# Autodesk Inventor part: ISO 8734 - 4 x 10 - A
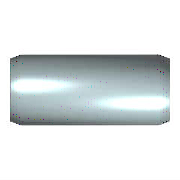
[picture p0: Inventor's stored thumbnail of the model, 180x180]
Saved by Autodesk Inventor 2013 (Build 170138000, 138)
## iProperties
IsCustomPart: 0
Created: 2012-02
Part Number: ISO 8734 - 4 x 10 - A
Material: Stahl
Description: Zylinderstift
Document SubType Name: Modeling
Standard: ISO 8734
Designer: rYan
Standards Organization: DIN
Language: de-DE
Size Designation: 4 x 10 - A
Categories: <MemberInstance><Categories><Category DisplayName="Verbindungselemente" InternalName="e4da775c-781d-43d5-af7c-5136215cf5a6" Mnemonic="FSTN"><Category DisplayNam
Density: 7.85 g/cm^3
Mass: 0.976264 g
Surface Area: 1.466 cm^2
Volume: 0.124365 cm^3
Author: rYan
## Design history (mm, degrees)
sketch "Skizze"
  geometry: C1 r 2 at (0, 0); 1 further point
  constraints: 1 centre point, 1 coincident
  dimensions: "d1" = 4 diameter of C1 (= NND)
extrude "Körper" new body sketch "Skizze" distance "d2" = 10 (= NLG); taper "d3" = 0 deg
body "Solid1"
chamfer "Fase1" distance "d4" = 0.63 (= PHH); stored, may be unused: angle "d5" = 15 deg (= FAWI), second distance "d11" = 0.63 (= PHH)
chamfer "Fase2" distance "d8" = 0.63 (= PHH); stored, may be unused: angle "d9" = 15 deg (= FAWI), second distance "d12" = 0.63 (= PHH)
other parameters: "NND" = 4 [user parameter; used in 1 equation term], "NLG" = 10 [user parameter; used in 1 equation term], "PHH" = 0.63 [user parameter; used in 5 equation terms], "FAWI" = 15 deg [user parameter; used in 2 equation terms], "d13" = 0, "d15" = 0, "d16" = 0, "PHH2" = 0.63 (= PHH) [user parameter], "FAWI2" = 15 deg [user parameter]
